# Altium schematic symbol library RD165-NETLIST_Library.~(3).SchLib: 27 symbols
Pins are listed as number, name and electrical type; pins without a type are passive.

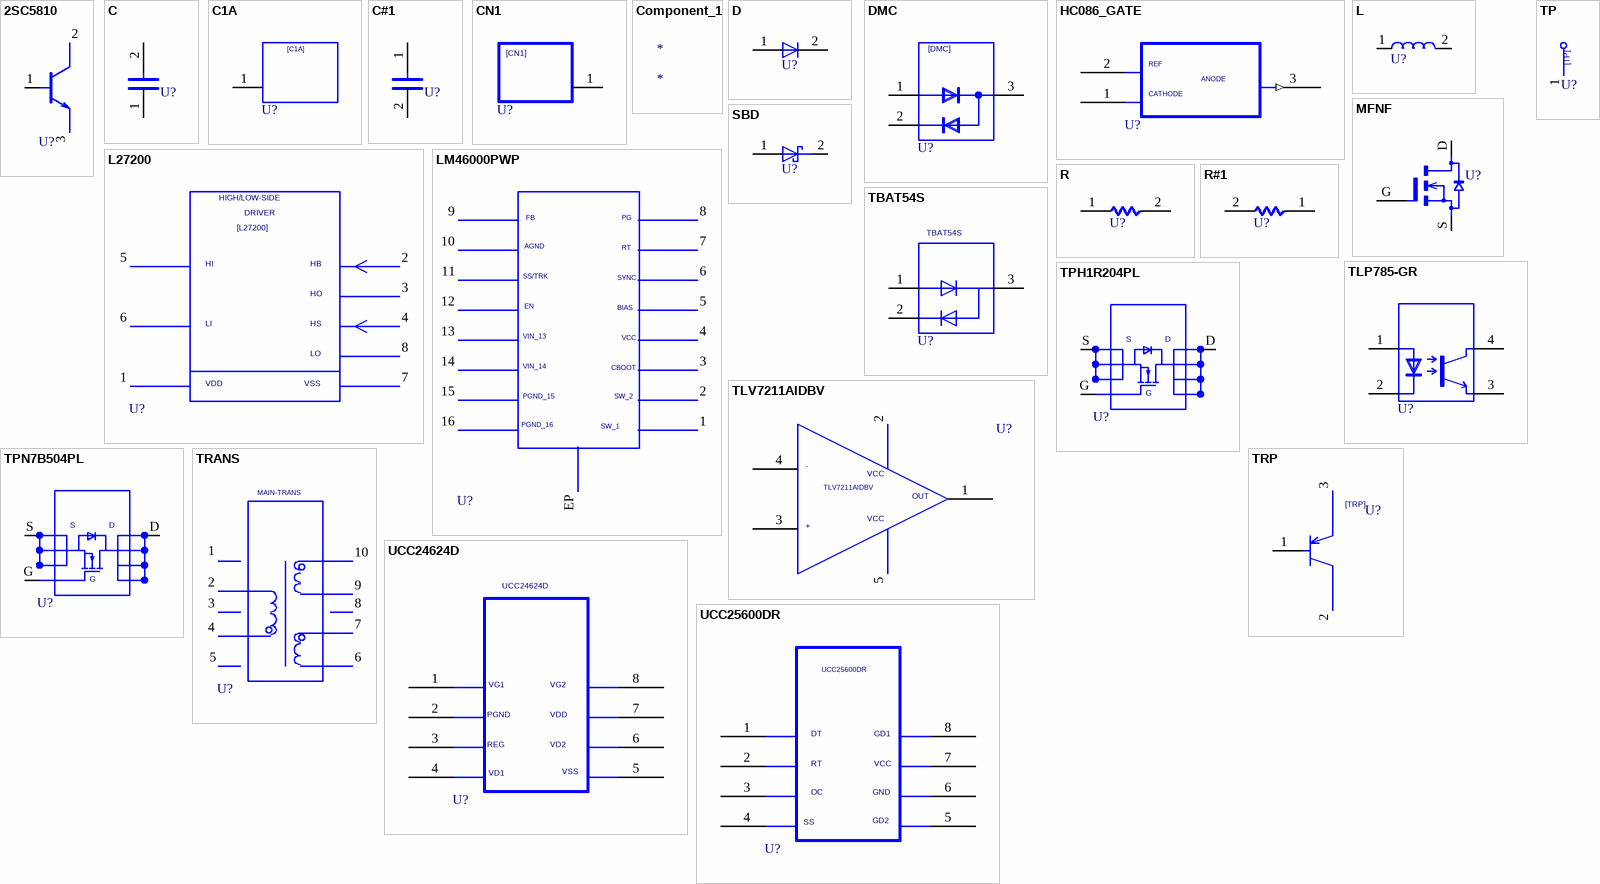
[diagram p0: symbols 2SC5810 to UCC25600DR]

## 2SC5810
designator U?  (value not drawn)
DEVICENAME: 2SC2712-Y; SAVECOUNT: 8; SAVEAREA0: -35656,-18339,48402,18661; TIME: 17:21:57; UPDATEUSER: t5459927; UPDATETIME: 15:35:42; OriginalSymbolOrigin: (2540,10160); Altium-Right: 20; Altium-Bottom: 80
pins: 1 (io), 2 (io), 3 (io)

## C
designator U?  (value not drawn)
OriginalSymbolOrigin: (2540,7620); Altium-Right: 20; Altium-Bottom: 10
pins: 1, 2

## C1A
designator U?  (value not drawn)
SAVEAREA0: -2398,-158,22444,15662; SAVECOUNT: 23; TIME: 13:28:28; UPDATEUSER: 19910145; UPDATETIME: 08:46:11; OriginalSymbolOrigin: (5080,12700); Altium-Right: 50; Altium-Bottom: 40
pins: 1

## C#1
designator U?, comment C  (value not drawn)
OriginalSymbolOrigin: (2540,7620); Altium-Right: 20; Altium-Bottom: 10
pins: 1 2, 2 1

## CN1
designator U?  (value not drawn)
OriginalSymbolOrigin: (2540,12700); Altium-Right: 50; Altium-Bottom: 40
pins: 1

## Component_1
designator *

## D
designator U?  (value not drawn)
SAVEAREA0: -225,-91,12804,7836; SAVECOUNT: 3; TIME: 14:49:55; UPDATEUSER: 19870035; UPDATETIME: 14:20:16; OriginalSymbolOrigin: (5080,5080); Altium-Right: 10; Altium-Bottom: 20
pins: 1 A, 2 C

## DMC
designator U?  (value not drawn)
OriginalSymbolOrigin: (5080,20320); Altium-Right: 50; Altium-Bottom: 70
pins: 1 A, 2 C, 3 AC

## HC086_GATE
designator U?  (value not drawn)
SAVEAREA0: -52989,-44408,93321,62857; TIME: 17:36:35; UPDATEUSER: t5459927; UPDATETIME: 16:48:34; SAVECOUNT: 2; OriginalSymbolOrigin: (7620,15240); Altium-Right: 100; Altium-Bottom: 50
pins: 1 A1, 2 A0, 3 A2 (out)

## L
designator U?  (value not drawn)
OriginalSymbolOrigin: (2540,5080); Altium-Right: 30; Altium-Bottom: 20
pins: 1, 2

## L27200
designator U?  (value not drawn)
SAVEAREA0: -11719,-442,57445,43603; SAVECOUNT: 88; TIME: 14:04:55; UPDATEUSER: 19910145; UPDATETIME: 08:40:41; OriginalSymbolOrigin: (0,40640); Altium-Right: 190; Altium-Bottom: 140
pins: 1, 2, 3, 4, 5, 6, 7, 8

## LM46000PWP
designator U?  (value not drawn)
SAVEAREA0: -103229,-18837,147120,85898; SAVECOUNT: 12; TIME: 10:30:02; UPDATEUSER: t5459927; UPDATETIME: 10:58:41; OriginalSymbolOrigin: (0,45720); Altium-Right: 160; Altium-Bottom: 210
pins: 1, 2, 3, 4, 5, 6, 7, 8, 9, 10, 11, 12, 13, 14, 15, 16, EP

## MFNF
designator U?  (value not drawn)
SAVECOUNT: 13; SAVEAREA0: -36202,-24391,51351,39797; TIME: 17:06:19; UPDATEUSER: t5459927; UPDATETIME: 17:07:36; OriginalSymbolOrigin: (5080,12700); Altium-Right: 40
pins: D, G, S

## R
designator U?  (value not drawn)
OriginalSymbolOrigin: (5080,5080); Altium-Right: 20
pins: 1, 2

## R#1
designator U?, comment R  (value not drawn)
OriginalSymbolOrigin: (5080,5080); Altium-Right: 20
pins: 1 2, 2 1

## SBD
designator U?  (value not drawn)
SAVEAREA0: -4630,-153,17114,13055; TIME: 14:49:55; UPDATEUSER: fukuda-y; UPDATETIME: 08:16:22; SAVECOUNT: 9; OriginalSymbolOrigin: (5080,5080); Altium-Right: 20
pins: 1 A, 2 C

## TBAT54S
designator U?  (value not drawn)
SAVEAREA0: -9930,-5308,32601,25918; TIME: 14:49:55; UPDATEUSER: t5459927; UPDATETIME: 18:16:07; SAVECOUNT: 5; OriginalSymbolOrigin: (5080,17780); Altium-Right: 50; Altium-Bottom: 60
pins: 1, 2, 3

## TLP785-GR
designator U?  (value not drawn)
SAVEAREA0: -14986,-1554,37270,22534; TIME: 18:29:30; UPDATEUSER: t5459927; UPDATETIME: 17:04:25; SAVECOUNT: 2; OriginalSymbolOrigin: (5080,17780); Altium-Right: 50; Altium-Bottom: 70
pins: 1, 2, 3, 4

## TLV7211AIDBV
designator U?  (value not drawn)
SAVECOUNT: 19; SAVEAREA0: -11523,-10867,52370,35975; TIME: 20:02:00; UPDATEUSER: t5459927; UPDATETIME: 08:40:37; OriginalSymbolOrigin: (7620,25400); Altium-Right: 100
pins: 1, 2, 3, 4, 5

## TP
designator U?  (value not drawn)
TIME: 16:12:21; UPDATEUSER: fukuda-y; UPDATETIME: 16:18:11; SAVECOUNT: 2; SAVEAREA0: -242,-92,12810,7836; OriginalSymbolOrigin: (0,7620); Altium-Right: 20; Altium-Bottom: 30
pins: 1

## TPH1R204PL
designator U?  (value not drawn)
SAVEAREA0: -12288,2904,25804,30831; TIME: 18:57:44; UPDATEUSER: t5459927; UPDATETIME: 10:59:26; SAVECOUNT: 20; OriginalSymbolOrigin: (2540,20320); Altium-Right: 70
pins: D, G, S

## TPN7B504PL
designator U?  (value not drawn)
SAVEAREA0: -19306,-3375,26732,30377; TIME: 18:57:44; UPDATEUSER: t5459927; UPDATETIME: 10:59:22; SAVECOUNT: 23; OriginalSymbolOrigin: (2540,20320); Altium-Right: 70
pins: D, G, S

## TRANS
designator U?  (value not drawn)
TIME: 11:13:20; UPDATEUSER: t5459927; UPDATETIME: 08:15:09; SAVECOUNT: 11; SAVEAREA0: -41965,-13400,68708,37616; OriginalSymbolOrigin: (-2540,33020); Altium-Right: 110; Altium-Bottom: 120
pins: 1, 2, 3, 4, 5, 6, 7, 8, 9, 10

## TRP
designator U?  (value not drawn)
TIME: 09:39:04; UPDATEUSER: 19870035; UPDATETIME: 15:34:42; SAVECOUNT: 12; SAVEAREA0: -5466,-244,29263,20886; OriginalSymbolOrigin: (5080,22860); Altium-Right: 20; Altium-Bottom: 100
pins: 1 B, 2 C, 3 E

## UCC24624D
designator U?  (value not drawn)
TIME: 09:07:35; UPDATEUSER: t5459927; UPDATETIME: 09:15:01; SAVECOUNT: 2; SAVEAREA0: -23382,-806,66635,38817; OriginalSymbolOrigin: (7620,35560); Altium-Right: 110; Altium-Bottom: 130
pins: 1, 2, 3, 4, 5, 6, 7, 8

## UCC25600DR
designator U?  (value not drawn)
SAVEAREA0: -5309,-792,48736,38830; TIME: 17:00:15; UPDATEUSER: t5459927; UPDATETIME: 08:35:41; SAVECOUNT: 3; OriginalSymbolOrigin: (7620,35560); Altium-Right: 110; Altium-Bottom: 130
pins: 1, 2, 3, 4, 5, 6, 7, 8

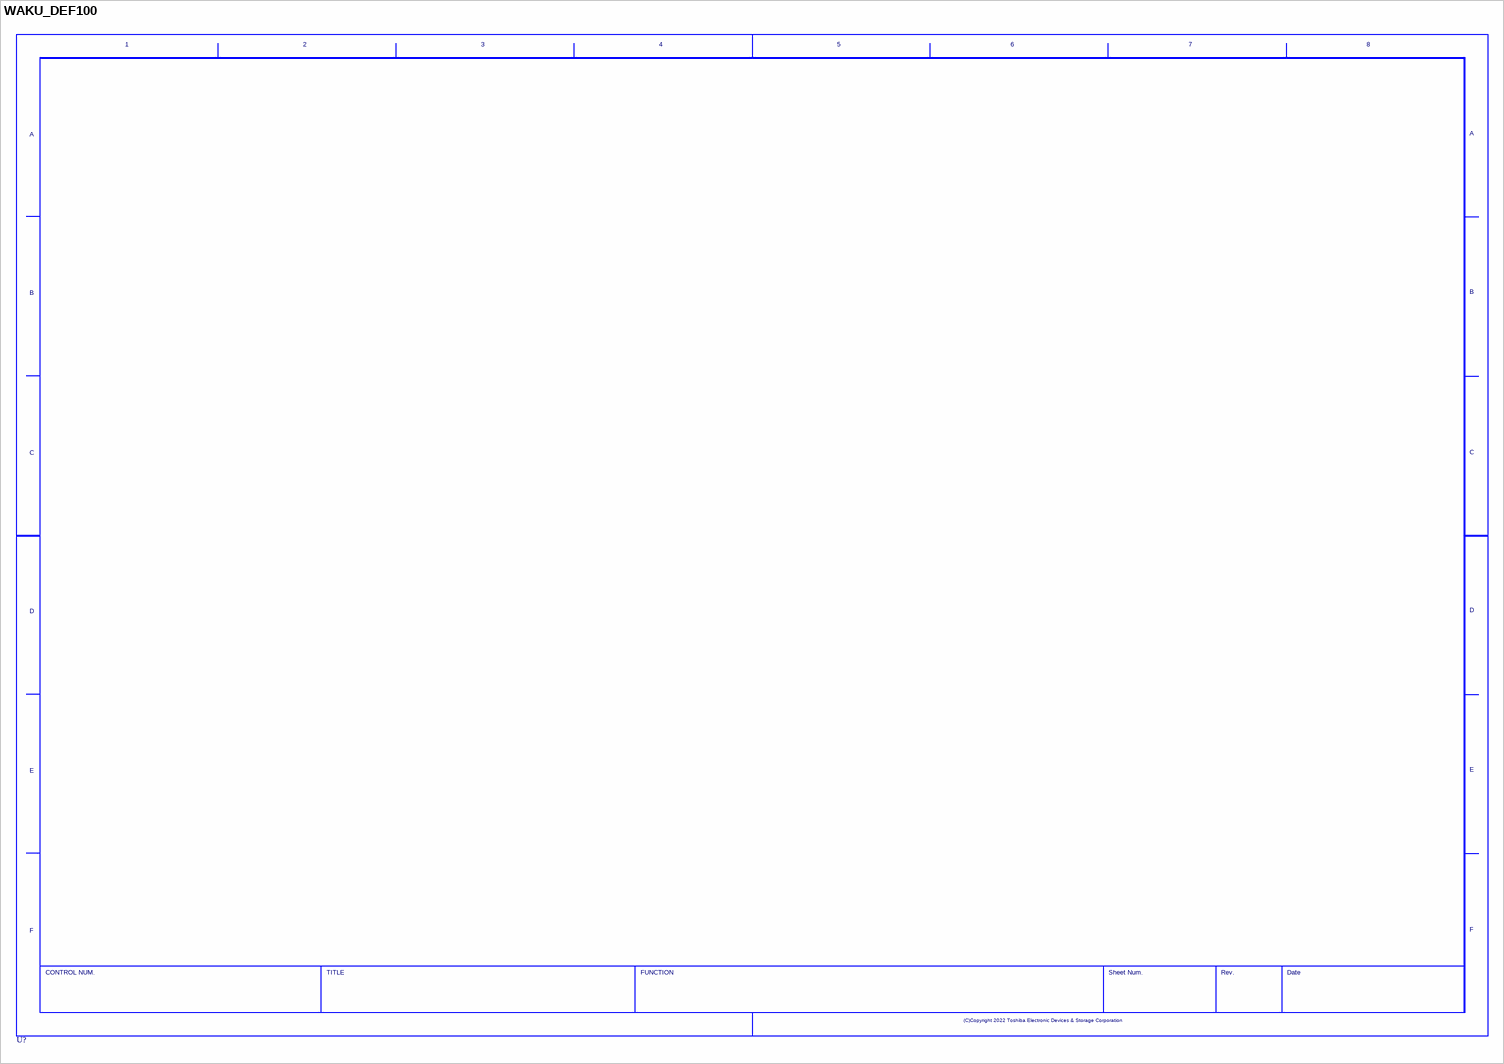
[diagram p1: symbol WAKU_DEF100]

## WAKU_DEF100
designator U?  (value not drawn)
PLOTTIME: HH:MM; SAVEAREA0: 218113,-61071,416451,84337; TIME: 14:30:25; UPDATEUSER: t5459927; UPDATETIME: 16:40:50; SAVECOUNT: 7; OriginalSymbolOrigin: (10160,284480); Altium-Right: 1570; Altium-Bottom: 1070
